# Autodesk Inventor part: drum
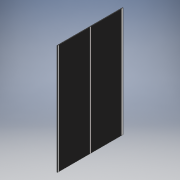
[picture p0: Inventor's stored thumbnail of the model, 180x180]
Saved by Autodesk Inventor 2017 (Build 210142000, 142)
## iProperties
Created: 2017-11
Part Number: drum
Material: Rubber
Document SubType Name: Modeling
Designer: iusti
Density: 0.93 g/cm^3
Appearance: Rubber - Black
Author: iusti
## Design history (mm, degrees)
sketch "Sketch1"
  geometry: L1 (3000, 5000)-(-3000, 5000); L2 (-3000, 5000)-(-3000, -5000); L3 (-3000, -5000)-(3000, -5000); L4 (3000, -5000)-(3000, 5000); L5 (3000, 5000)-(-3000, -5000); L6 (-3000, 5000)-(3000, -5000); 1 further point
  constraints: 12 end point, 2 midpoint, 2 parallel, 1 horizontal, 1 perpendicular
  dimensions: "d0" = 6000 distance of L1.start L1.end; "d1" = 10000 distance of L3.end L1.start
extrude "Extrusion1" new body sketch "Sketch1" distance "d2" = 50; taper "d3" = 0 deg
sketch "Sketch2"
  geometry: L1 (-5000, 50)-(5000, 50); L2 (-5000, -50)-(5000, -50); L3 (-5000, 3000)-(-5000, -3000) reference; L4 (5000, -3000)-(5000, 3000) reference; L5 (-5000, 50)-(-5000, -50); L6 (5000, 50)-(5000, -50); 1 further point
  constraints: 8 end point, 2 horizontal, 2 parallel
  dimensions: "d4" = 100 distance between parallel lines of L2 L1; "d5" = 10000 distance of L1.start L1.end; "d6" = 0 distance from line of L3 L1.start; "d7" = 0 distance from line of L4 L2.end; "d8" = 50 distance from line of point (0, 0) L1 (= 0.5 x d4)
extrude "Extrusion2" join sketch "Sketch2" distance "d9" = 0.5; taper "d10" = 0 deg
sketch "Sketch3"
  geometry: L1 (-5000, 1425)-(5000, 1425); L2 (-5000, 1325)-(5000, 1325); L3 (-5000, 4375)-(-5000, -1625); L4 (5000, -1625)-(5000, 4375); L5 (-5000, 1425)-(-5000, 1325); L6 (5000, 1425)-(5000, 1325); L7 (5000, 1475)-(-5000, 1475) reference; 1 further point
  constraints: 12 end point, 2 horizontal, 2 parallel
  dimensions: "d11" = 100 distance between parallel lines of L2 L1; "d14" = 10000 distance of L1.start L1.end; "d15" = 0 distance from line of L3 L1.start; "d12" = 0 distance from line of L4 L2.end; "d13" = 50 distance from line of point (0, 1375) L1 (= 0.5 x d11); "d19" = 50 distance between parallel lines of L1 L7
extrude "Extrusion3" join sketch "Sketch3" taper "d17" = 0 deg; distance "d18" = 0.5
sketch "Sketch4"
  geometry: L1 (-5000, -1325)-(5000, -1325); L2 (-5000, -1425)-(5000, -1425); L3 (-5000, 1625)-(-5000, -4375); L4 (5000, -4375)-(5000, 1625); L5 (-5000, -1325)-(-5000, -1425); L6 (5000, -1325)-(5000, -1425); L7 (-5000, -1475)-(5000, -1475) reference; 1 further point
  constraints: 12 end point, 2 horizontal, 2 parallel
  dimensions: "d20" = 100 distance between parallel lines of L2 L1; "d23" = 10000 distance of L1.start L1.end; "d24" = 0 distance from line of L3 L1.start; "d21" = 0 distance from line of L4 L2.end; "d22" = 50 distance from line of point (0, -1375) L1 (= 0.5 x d20); "d28" = 50 distance between parallel lines of L7 L2
extrude "Extrusion4" join sketch "Sketch4" taper "d26" = 0 deg; distance "d27" = 0.5
body "Solid1"
